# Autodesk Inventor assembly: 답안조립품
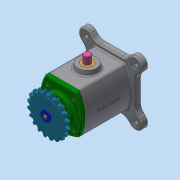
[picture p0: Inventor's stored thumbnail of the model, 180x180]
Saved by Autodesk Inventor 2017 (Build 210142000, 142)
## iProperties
Part Number: 답안조립품
Material: 일반
Document SubType Name: Assembly
Designer: Administrator
Author: Administrator
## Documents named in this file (13)
- C:\Users\Administrator\Desktop\720106V1008\답안조립품.iam
- C:\Users\Administrator\Desktop\720106V1008\베어링 6203.ipt
- C:\Users\Administrator\Desktop\720106V1008\본체.ipt
- C:\Users\Administrator\Desktop\720106V1008\볼트 M4 x 12.ipt
- C:\Users\Administrator\Desktop\720106V1008\부시.ipt
- C:\Users\Administrator\Desktop\720106V1008\스프로킷.ipt
- C:\Users\Administrator\Desktop\720106V1008\슬라이더.ipt
- C:\Users\Administrator\Desktop\720106V1008\오일 실 17 x 30 x 8.ipt
- C:\Users\Administrator\Desktop\720106V1008\와셔 4 x 20.ipt
- C:\Users\Administrator\Desktop\720106V1008\육각머리볼트 M4.ipt
- C:\Users\Administrator\Desktop\720106V1008\커버.ipt
- C:\Users\Administrator\Desktop\720106V1008\키 5 x 5.ipt
- C:\Users\Administrator\Desktop\720106V1008\편심축.ipt
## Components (8 placed, 1 different names)
1. M4x0.7x12:1
2. M4x0.7x12:3
3. M4x0.7x12:4
4. M4x0.7x12:5
5. M4x0.7x12:2
6. M4x0.7x12:6
7. M4x0.7x12:7
8. M4x0.7x12:8
